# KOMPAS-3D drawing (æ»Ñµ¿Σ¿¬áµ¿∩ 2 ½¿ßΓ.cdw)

Referenced files: Спецификация 2 лист.cdw
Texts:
  Текст на чертеже
  Размерные надписи
  Шероховатость
  Линия-выноска #1
  Линия-выноска #2
  Линия-выноска #3
  Отклонения формы и база
  Заголовок таблицы
  Ячейка таблицы
  Стрелка вида
  Обозначение изменения
  Фигурная скобка
  Номер узла
  Марка координационной оси
  VRCB
  Выносная надпись
  Обозначение узла
  Марка/позиционное обозначение с линией-выноской
  Марка/позиционное обозначение на линии
  Марка/позиционное обозначение без линии-выноски
  ГОСТ 8338-75
  Шпилька М16х60 20 42 58
  ГОСТ 122038-76
Dimensions and other numbers on the sheet: 7; 4; 1:1; 15; 16; 17; 3; 2; 0; 1; 5; 6; 8; 9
